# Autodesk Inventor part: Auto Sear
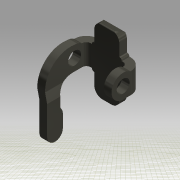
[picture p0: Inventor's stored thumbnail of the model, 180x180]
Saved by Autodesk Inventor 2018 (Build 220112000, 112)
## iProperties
Created: 2019-01
Part Number: Auto Sear
Material: Generic
Document SubType Name: Modeling
Designer: johne
Appearance: Default
Author: johne
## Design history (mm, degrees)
feature "Solid2"
body "Solid1"
